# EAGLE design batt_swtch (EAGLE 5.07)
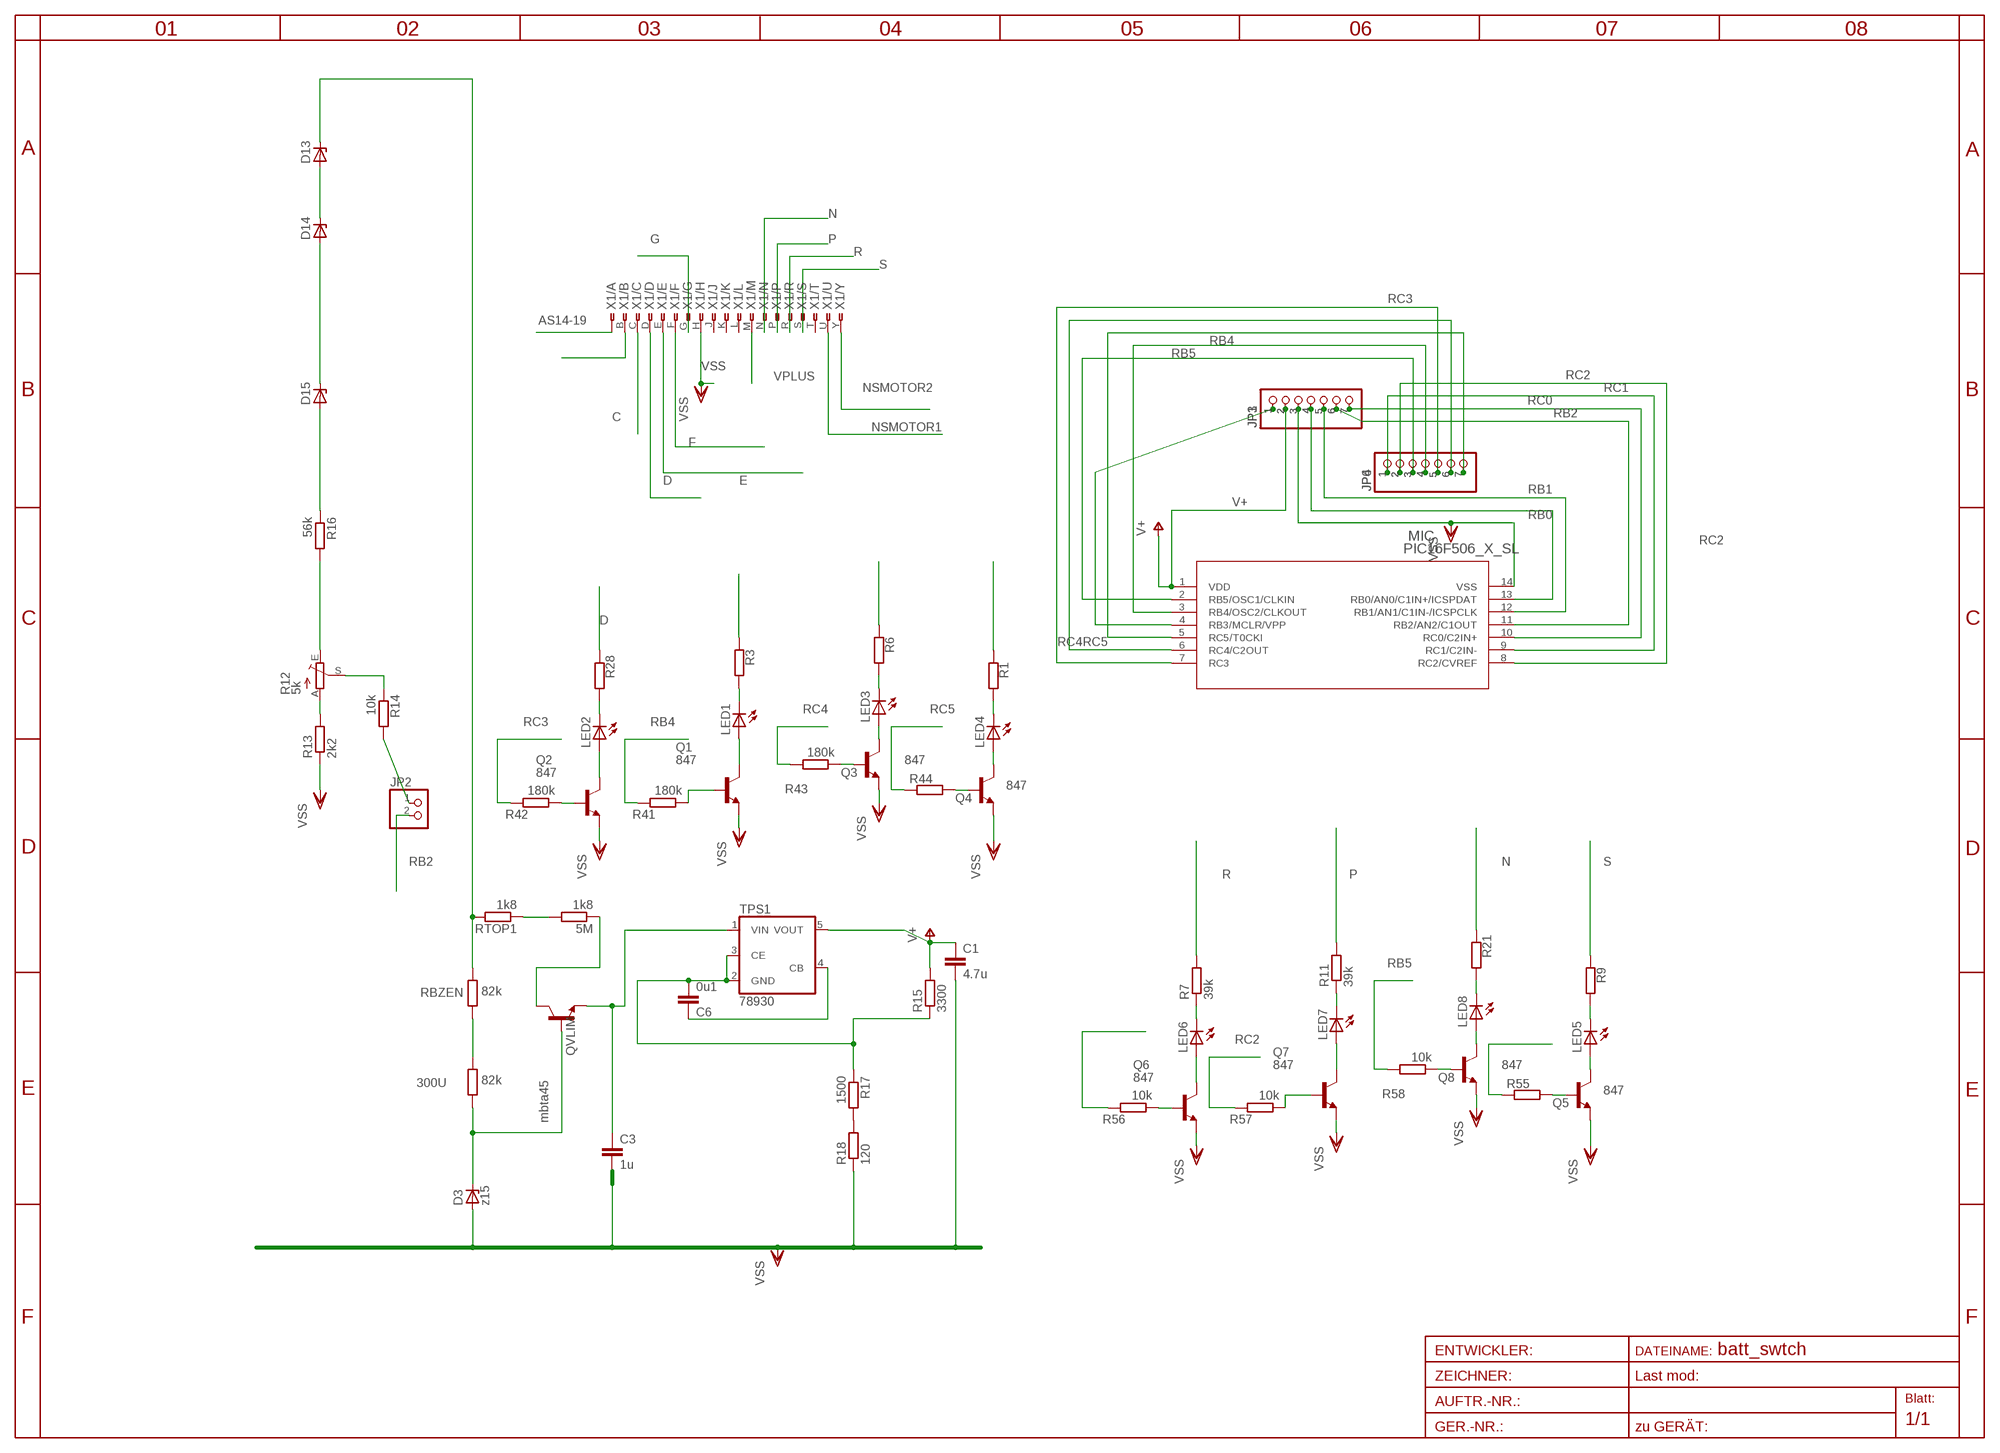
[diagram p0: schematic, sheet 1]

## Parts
5M  1k8  R-EU_R1206  [R1206]
300U  82k  R-EU_R1206  [R1206]
C1  4.7u  C-EUC1206  [C1206]
C3  1u  C-EUC1206  [C1206]
C6  0u1  C-EUC0805  [C0805]
D3  z15  ZENER-DIODESOD80C  [SOD80C]
D13  ZENER-DIODESOD80C  [SOD80C]
D14  ZENER-DIODESOD80C  [SOD80C]
D15  ZENER-DIODESOD80C  [SOD80C]
JP1  PINHD-1X7  [1X07]
JP2  PINHD-1X2STR  [1X02]
JP3  PINHD-1X7  [1X07]
JP4  PINHD-1X7  [1X07]
JP6  PINHD-1X7  [1X07]
LED1  LEDCHIPLED_1206  [CHIPLED_1206]
LED2  LEDCHIPLED_1206  [CHIPLED_1206]
LED3  LEDCHIPLED_1206  [CHIPLED_1206]
LED4  LEDCHIPLED_1206  [CHIPLED_1206]
LED5  LEDCHIPLED_1206  [CHIPLED_1206]
LED6  LEDCHIPLED_1206  [CHIPLED_1206]
LED7  LEDCHIPLED_1206  [CHIPLED_1206]
LED8  LEDCHIPLED_1206  [CHIPLED_1206]
MIC  PIC16F506_X_SL  [SOIC14_N_MC]
Q1  847  BC847ASMD  [SOT23]
Q2  847  BC847ASMD  [SOT23]
Q3  847  BC847ASMD  [SOT23]
Q4  847  BC847ASMD  [SOT23]
Q5  847  BC847ASMD  [SOT23]
Q6  847  BC847ASMD  [SOT23]
Q7  847  BC847ASMD  [SOT23]
Q8  847  BC847ASMD  [SOT23]
QVLIM  mbta45  BC847ALT1SMD  [SOT23]
R1  0  R-EU_R0805  [R0805]
R3  0  R-EU_R0805  [R0805]
R6  0  R-EU_R0805  [R0805]
R7  39k  R-EU_R0805  [R0805]
R9  39k  R-EU_R0805  [R0805]
R11  39k  R-EU_R0805  [R0805]
R12  5k  TRIM_EU-S64W  [S64W]
R13  2k2  R-EU_R0805  [R0805]
R14  10k  R-EU_R0805  [R0805]
R15  3300  R-EU_R0805  [R0805]
R16  56k  R-EU_R0805  [R0805]
R17  1500  R-EU_R0805  [R0805]
R18  120  R-EU_R0805  [R0805]
R21  39k  R-EU_R0805  [R0805]
R28  39k  R-EU_R0805  [R0805]
R41  180k  R-EU_R0805  [R0805]
R42  180k  R-EU_R0805  [R0805]
R43  180k  R-EU_R0805  [R0805]
R44  0  R-EU_R0805  [R0805]
R55  10k  R-EU_R0805  [R0805]
R56  10k  R-EU_R0805  [R0805]
R57  10k  R-EU_R0805  [R0805]
R58  10k  R-EU_R0805  [R0805]
RBZEN  82k  R-EU_R1206  [R1206]
RTOP1  1k8  R-EU_R1206  [R1206]
TPS1  78930  TPS78930SOT23-5  [SOT25]
X1  AS14-19  AS14-19OLIVE  [Y28M-19TK]

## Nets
C: R3.2 X1.C
CB: 300U.2 D3.C QVLIM.1(B)
D: R28.2 X1.D
E: R6.2 X1.E
F: R1.2 X1.F
G: X1.G
GND1: C6.1 TPS1.4(CB)
N: R21.2 X1.N
N$1: 300U.1 RBZEN.2
N$2: LED4.A Q4.3(C)
N$3: R12.E R16.2
N$4: Q8.1(B) R58.1
N$5: R12.S R14.1
N$6: Q3.1(B) R43.1
N$7: LED4.C R1.1
N$8: R17.2 R18.2
N$9: LED2.A Q2.3(C)
N$10: LED2.C R28.1
N$11: Q2.1(B) R42.1
N$12: Q1.1(B) R41.1
N$13: LED3.A Q3.3(C)
N$14: Q5.1(B) R55.1
N$15: LED1.C R3.1
N$16: 5M.1 QVLIM.3(C)
N$17: LED5.A Q5.3(C)
N$18: D15.A R16.1
N$19: LED1.A Q1.3(C)
N$20: LED3.C R6.1
N$21: JP2.1 R14.2
N$22: LED5.C R9.1
N$23: D14.A D15.C
N$24: D13.A D14.C
N$25: LED6.A Q6.3(C)
N$26: R12.A R13.2
N$27: LED6.C R7.1
N$28: Q6.1(B) R56.1
N$29: 5M.2 RTOP1.1
N$30: Q4.1(B) R44.1
N$31: Q7.1(B) R57.1
N$32: LED8.A Q8.3(C)
N$33: LED7.C R11.1
N$34: X1.A
N$35: X1.B
N$36: LED7.A Q7.3(C)
N$37: LED8.C R21.1
NSMOTOR1: X1.U
NSMOTOR2: X1.Y
P: R11.2 X1.P
R: R7.2 X1.R
RB0: JP1.4 JP3.4 MIC.13(RB0/AN0/C1IN+/ICSPDAT)
RB1: JP1.5 JP3.5 MIC.12(RB1/AN1/C1IN-/ICSPCLK)
RB2: JP1.6 JP2.2 JP3.6 MIC.11(RB2/AN2/C1OUT)
RB4: JP4.4 JP6.4 MIC.3(RB4/OSC2/CLKOUT) R41.2
RB5: JP4.3 JP6.3 MIC.2(RB5/OSC1/CLKIN) R58.2
RC0: JP1.7 JP3.7 MIC.10(RC0/C2IN+) R55.2
RC1: JP4.1 JP6.1 MIC.9(RC1/C2IN-) R56.2
RC2: JP4.2 JP6.2 MIC.8(RC2/CVREF) R57.2
RC3: JP4.5 JP6.5 MIC.7(RC3) R42.2
RC4: JP4.6 JP6.6 MIC.6(RC4/C2OUT) R43.2
RC5: JP4.7 JP6.7 MIC.5(RC5/T0CKI) R44.2
S: R9.2 X1.S
V15: C3.1 QVLIM.2(E) TPS1.1(VIN)
V+: C1.1 JP1.2 JP3.2 MIC.1(VDD) R15.2 TPS1.5(VOUT)
V-: C6.2 R15.1 R17.1 TPS1.2(GND) TPS1.3(CE)
VPLUS: D13.C RBZEN.1 RTOP1.2 X1.M
VSS: C1.2 C3.2 D3.A JP1.3 JP3.3 MIC.14(VSS) Q1.2(E) Q2.2(E) Q3.2(E) Q4.2(E) Q5.2(E) Q6.2(E) Q7.2(E) Q8.2(E) R13.1 R18.1 X1.H
WIND: JP1.1 JP3.1 MIC.4(RB3/MCLR/VPP)
Unconnected: X1.J X1.K X1.L X1.T

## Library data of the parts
5M 300U R13-R18 RBZEN RTOP1 = rcl:R-EU_: RESISTOR, European symbol
C1 C3 C6 = rcl:C-EU: CAPACITOR, European symbol
D3 D13-D15 = diode:ZENER-DIODE: Z-Diode
JP1 JP3 JP4 JP6 = pinhead:PINHD-1X7: PIN HEADER
JP2 = pinhead:PINHD-1X2: PIN HEADER
LED1-LED8 = led:LED: LED
MIC = pic16f506mc:PIC16F506_X_SL
Q1-Q8 QVLIM = transistor-npn:BC847*: NPN Transistor
R1 R3 R6 R7 R9 R11 R21 R28 R41-R44 R55-R58 = rcl-2:R-EU_: RESISTOR, European symbol
R12 = pot:TRIM_EU-: POTENTIOMETER
TPS1 = v-reg:TPS78930
X1 = con-deutsch:AS14-19: DEUTSCH Connector

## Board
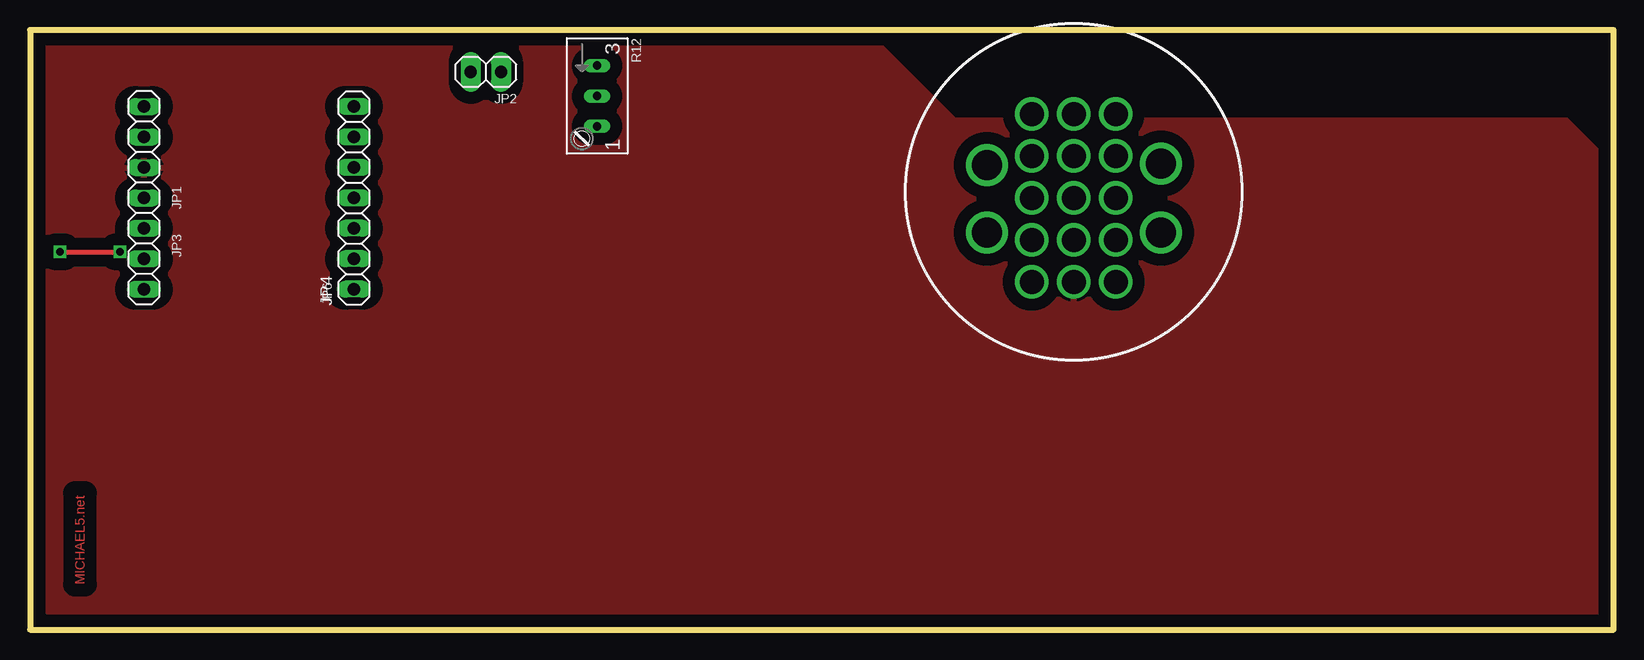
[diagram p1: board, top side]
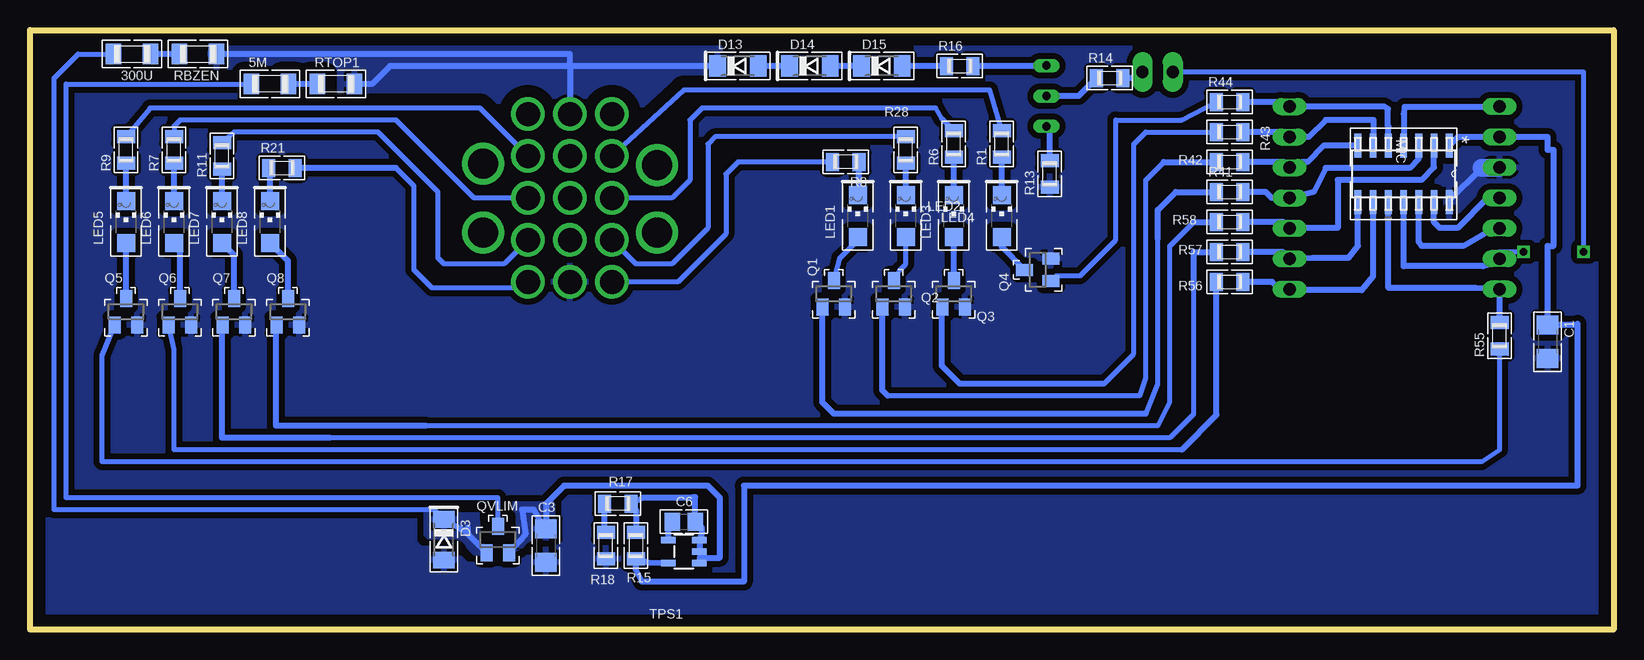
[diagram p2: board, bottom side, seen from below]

Size 132 x 50 mm. Coordinates in mm from the lower left corner, seen from the top.
Outline: 132,0 132,50 0,50 0,0 132,0
Copper layers (1*16): Top 0.035mm / dielectric 1.5mm / Bottom 0.035mm
Design rules "default *": minimum track width 40mil, minimum drill 30mil, track to track 8mil, track to pad 8mil, pad to pad 8mil, via to via 8mil, smd to smd 8mil, copper to edge 40mil, drill to drill 8mil, minimum pad ring 8mil, minimum via ring 8mil, stop-mask expansion 4mil, vias tented up to drill 0mil, thermal gap 10mil

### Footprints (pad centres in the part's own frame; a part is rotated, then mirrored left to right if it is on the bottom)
R1206 = smd 1.3 x 1.7: 1 -1.55,0; 2 1.55,0
C1206 = smd 1.6 x 1.8: 1 -1.4,0; 2 1.4,0
C0805 = smd 1.3 x 1.5: 1 -0.95,0; 2 0.95,0
SOD80C = smd 1.4 x 1.8: A 1.7,0; C -1.7,0
1X07 = drill 1.016 long: 1 -7.62,0; 2 -5.08,0; 3 -2.54,0; 4 0,0; 5 2.54,0; 6 5.08,0; 7 7.62,0
1X02 = drill 1.016 pad 1.676 long: 1 -1.27,0; 2 1.27,0
CHIPLED_1206 = smd 1.5 x 1.5: A 0,-1.75; C 0,1.75
SOIC14_N_MC = smd 1.981 x 0.559: 1 -2.362,3.81; 2 -2.362,2.54; 3 -2.362,1.27; 4 -2.362,0; 5 -2.362,-1.27; 6 -2.362,-2.54; 7 -2.362,-3.81; 8 2.362,-3.81; 9 2.362,-2.54; 10 2.362,-1.27; 11 2.362,0; 12 2.362,1.27; 13 2.362,2.54; 14 2.362,3.81
SOT23 = smd 1 x 1.4: 1 -0.95,-1.1; 2 0.95,-1.1; 3 0,1.1
R0805 = smd 1.1 x 1.5: 1 -1.1,0; 2 1.1,0
S64W = drill 0.7 long: A 2.54,1.27; E -2.54,1.27; S 0,1.27
SOT25 = smd 0.55 x 1.2: 1 -0.95,-1.3; 2 0,-1.3; 3 0.95,-1.3; 4 0.95,1.3; 5 -0.95,1.3
Y28M-19TK = drill 2.5 pad 3.5 round: A -7.25,-2.875; B -7.25,2.75; U 7.25,-2.875; Y 7.25,2.875 | drill 2 pad 2.54 round: C -3.5,-7; D -3.5,-3.5; E -3.5,0; F -3.5,3.5; G -3.5,7; H 0,-7; J 0,-3.5; K 0,0; L 0,3.5; M 0,7; N 3.5,-7; P 3.5,-3.5; R 3.5,0; S 3.5,3.5; T 3.5,7

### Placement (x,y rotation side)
5M  112,45.5 0 bottom
300U  123.5,48 180 bottom
C1  5.5,24 270 bottom
C3  89,7 270 bottom
C6  77.5,9 0 bottom
D3  97.5,7.5 270 bottom
D13  73,47 0 bottom
D14  67,47 0 bottom
D15  61,47 0 bottom
JP1  9.5,36 270 top
JP2  38,46.5 180 top
JP3  9.5,36 270 top
JP4  27,36 90 top
JP6  27,36 90 top
LED1  63,34.5 0 bottom
LED2  59,34.5 0 bottom
LED3  55,34.5 0 bottom
LED4  51,34.5 0 bottom
LED5  124,34 0 bottom
LED6  120,34 0 bottom
LED7  116,34 0 bottom
LED8  112,34 0 bottom
MIC  17.5,38 270 bottom
Q1  65,28 0 bottom
Q2  60,28 0 bottom
Q3  55,28 0 bottom
Q4  48,30 90 bottom
Q5  124,26.5 0 bottom
Q6  119.5,26.5 0 bottom
Q7  115,26.5 0 bottom
Q8  110.5,26.5 0 bottom
QVLIM  93,7.5 0 bottom
R1  51,40.5 90 bottom
R3  64,39 180 bottom
R6  55,40.5 90 bottom
R7  120,40 90 bottom
R9  124,40 90 bottom
R11  116,39.5 90 bottom
R12  46,44.5 270 top
R13  47,38 90 bottom
R14  42,46 0 bottom
R15  81.5,7 270 bottom
R16  54.5,47 0 bottom
R17  83,10.5 180 bottom
R18  84,7 90 bottom
R21  111,38.5 0 bottom
R28  59,40 90 bottom
R41  32,36.5 0 bottom
R42  32,39 0 bottom
R43  32,41.5 0 bottom
R44  32,44 0 bottom
R55  9.5,24.5 90 bottom
R56  32,29 0 bottom
R57  32,31.5 0 bottom
R58  32,34 0 bottom
RBZEN  118,48 180 bottom
RTOP1  106.5,45.5 0 bottom
TPS1  77.5,6.5 90 bottom
X1  87,36 0 top

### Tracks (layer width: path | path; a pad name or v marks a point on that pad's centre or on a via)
C
  Bottom 0.406: R3.2 73,39 74,38 74,33 78,29 X1.C
CB
  Bottom 0.406: 300U.2 128,48 130,46 130,10 98.3,10 D3.C
  Bottom 0.5: QVLIM.1 95.5,7.95 95.5,8.5 95.8,8.2 D3.C
  pour Bottom (isolate 1, rank 3): 94,10.5 98.5,10.5 99,10 99,8 98.5,7.5 96,7.5 94.5,6 94,6 93.5,6.5 93.5,10
D
  Bottom 0.406: R28.2 74.9,41.1 75.5,40.5 75.5,33.5 78.5,30.5 81.5,30.5 X1.D
E
  Bottom 0.406: X1.E 78.5,36 77,37.5 77,42.5 76,43.5 56.5,43.5 56,42.6 R6.2
F
  Bottom 0.406: R1.2 52,45 77.5,45 X1.F
GND1
  Bottom 0.5: TPS1.4 78.8,8.65 C6.1
N
  Bottom 0.406: 101.5,38.5 100,37 100,30 98.5,28.5 91,28.5 X1.N
  Bottom 0.5: 101.5,38.5 R21.2
N$1
  Bottom 0.5: RBZEN.2 300U.1
N$2
  Bottom 0.5: LED4.A 51,31.9 Q4.3
N$3
  Bottom 0.5: R16.2 48,47 47.96,47.04 R12.E
N$4
  Bottom 0.406: 99,17 38,17 37,19 37,32 35,34
  Bottom 0.5: Q8.1 111.5,25.35 111.5,17 99,17 | 35,34 R58.1
N$5
  Bottom 0.5: R12.S 44.6,44.5 R14.1
N$6
  Bottom 0.406: R43.1 39,41.5 40,40.5 40,23 42.5,20.5
  Bottom 0.5: 42.5,20.5 54.5,20.5 56,22 56,26.85 Q3.1
N$7
  Bottom 0.5: LED4.C R1.1
N$8
  Bottom 0.5: R17.2 84.1,8.5 R18.2
N$9
  Bottom 0.406: LED2.A 59,30.5 59.5,30 Q2.3
N$10
  Bottom 0.5: LED2.C R28.1
N$11
  Bottom 0.406: 37.5,39 39,37.5 39,21 39.5,19.5 60.5,19.5
  Bottom 0.5: Q2.1 60.95,19.95 60.5,19.5 | 37.5,39 R42.1
N$12
  Bottom 0.406: 39,18 38,20.5 38,32.6
  Bottom 0.5: Q1.1 65.95,18.95 65,18 39,18 | 38,32.6 38,35 36.5,36.5 R41.1
N$13
  Bottom 0.5: Q3.3 LED3.A
N$14
  Bottom 0.406: R55.1 9.5,15 11,14 126,14 126,22.85 Q5.1
N$15
  Bottom 0.5: R3.1 62.9,36.35 LED1.C
N$16
  Bottom 0.406: 5M.1 129,45.5 129,11 93,11 QVLIM.3
N$17
  Bottom 0.5: Q5.3 LED5.A
N$18
  Bottom 0.5: R16.1 D15.A
N$19
  Bottom 0.406: LED1.A 63,32.5 64.5,31 Q1.3
N$20
  Bottom 0.5: LED3.C R6.1
N$21
  Bottom 0.5: R14.2 39.77,46 JP2.1
N$22
  Bottom 0.5: LED5.C R9.1
N$23
  Bottom 0.5: D15.C D14.A
N$24
  Bottom 0.5: D14.C D13.A
N$25
  Bottom 0.5: LED6.A 119.5,31.75 Q6.3
N$26
  Bottom 0.5: R13.2 47,41.69 R12.A
N$27
  Bottom 0.5: LED6.C R7.1
N$28
  Bottom 0.406: 36,15 120,15 120,23.35 Q6.1
  Bottom 0.5: R56.1 33.1,17.9 36,15
N$29
  Bottom 0.5: RTOP1.1 5M.2
N$30
  Bottom 0.406: R44.1 36,42.5 41.5,42.5 41.5,32.5 44.5,29.5 46.45,29.5 Q4.1
N$31
  Bottom 0.406: 35,28.5 35,18 37,16 107,16
  Bottom 0.5: Q7.1 116,25.35 116,16 107,16 | 35,28.5 35,31.5 R57.1
N$32
  Bottom 0.5: LED8.A 110.5,30.75 Q8.3
N$33
  Bottom 0.5: LED7.C R11.1
N$36
  Bottom 0.5: LED7.A 115,31.25 Q7.3
N$37
  Bottom 0.5: LED8.C 112,38.4 R21.1
P
  Bottom 0.406: R11.2 115,41.5 103,41.5 98,36.5 98,31 97.5,30.5 92.5,30.5 X1.P
R
  Bottom 0.406: R7.2 120,42 119.5,42.5 101.5,42.5 95,36 X1.R
RB0
  Bottom 0.5: JP3.4 9.54,35.96 10.54,35.96 13,33.5 14.5,33.5 14.96,33.96 MIC.13
RB1
  Bottom 0.5: JP3.5 9.54,33.5 10,33.5 9.97,33.47 9.97,33.42 12.5,32 16,32 16.2,32.31 16.23,32.34 MIC.12
RB2  (via drill 0.6)
  Top 0.406: v2.5,31.5 v7.5,31.5
  Bottom 0.406: JP2.2 2.5,46.5 v2.5,31.5 | v7.5,31.5 9.5,31.5 JP3.6
  Bottom 0.5: MIC.11 17.5,30.3 10.88,30.3 | 10.88,30.3 9.19,30.8 | JP3.6 10.88,30.3
RB4
  Bottom 0.5: MIC.3 16.23,39.27 17,38.5 24,38.5 25,36.5 JP6.4 28.5,36 29,36.5 R41.2
RB5
  Bottom 0.5: MIC.2 14.96,38.54 16,37.5 23,37.5 23,33.5 JP6.3 27.54,34 R58.2
RC0
  Bottom 0.5: MIC.10 18.77,28.5 11.5,28.5 8.73,28.3 9.42,28.3 JP3.7 R55.2
RC1
  Bottom 0.5: MIC.9 20.04,29.46 21,28.3 26.88,28.3 JP6.1 27.5,28.38 | 27.5,28.38 27.83,28.38 28.45,29 R56.2 | 27.5,28.38 27.62,28.5
RC2
  Bottom 0.5: MIC.8 21.31,31.99 22.1,31 25.08,31 JP6.2 27.58,31.5 R57.2
RC3
  Bottom 0.5: MIC.7 24.14,40.36 25.5,39 25.96,39 JP6.5 27.46,39 R42.2
RC4
  Bottom 0.5: MIC.6 20,40.4 20,42.5 24,42.5 25.42,41.08 JP6.6 27.42,41.5 R43.2
RC5
  Bottom 0.5: MIC.5 18.77,41.96 18.8,41.99 18.8,43.4 19.12,43.62 JP6.7 27.38,44 R44.2
S
  Bottom 0.406: R9.2 122,43.5 94.5,43.5 X1.S
V15
  Bottom 0.5: TPS1.1 76.15,6 74.5,6 74.5,11 75.5,12 87.5,12 89,10.5 C3.1 89.1,8.5 90,10 91,10 90.7,7.9 QVLIM.2
  pour Bottom (isolate 1, rank 3): 92,6.5 92,10.5 88.5,10.5 88.5,7.5 90,7.5
V+
  Bottom 0.5: TPS1.5 80.45,5.6 R15.2 81.5,5 81,4 72.5,4 72.5,12 3,12 3,25.5 3.1,25.4 C1.1 5.5,32 5,32 5,40 5.5,40 5.5,41.08 JP3.2 12.97,41.08 MIC.1
V-
  Bottom 0.5: TPS1.2 TPS1.3 76,8.15 76,8.5 76.55,9.05 C6.2 76.55,11.05 77,11 80.9,11 R17.1 81.9,10.4 81.5,10 R15.1
VPLUS
  Bottom 0.5: 87,47 X1.M | D13.C 87,47 | 87,47 102,47 103.5,45.5 RTOP1.2 | RBZEN.1 87,48 87,47
  pour Bottom (isolate 1): 74.5,48.5 116.5,48.5 117,48.5 117,45.5 115.5,44 91,44 89.5,42.5 80,42.5 76.5,46 74.5,46
VSS
  Bottom 0.5: MIC.14 13.69,35.81 11,38.5 | JP3.3 9.54,38.5
  Bottom 1.5: 9.54,38.5 11,38.5
  pour Bottom (isolate 0.5, rank 4): 1.5,50.5 132.5,50.5 132.5,1 0.5,1 0.5,7.5 0.5,47.5
  pour Top (isolate 1, rank 3): 1,48.5 71,48.5 77,42.5 128,42.5 128.5,42 131,39.5 131,1.5 130.5,1 2,1 1,2
WIND
  Bottom 0.5: MIC.4 17.5,43 17.42,43.58 9,43.58 | 9,43.58 8.57,43.58 | 9.5,43.5 JP3.1 9.04,43.62 9,43.58

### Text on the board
Top: MICHAEL5.net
